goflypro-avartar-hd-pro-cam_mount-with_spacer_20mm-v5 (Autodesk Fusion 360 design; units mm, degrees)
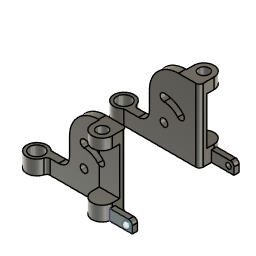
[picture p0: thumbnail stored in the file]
sketch "Skizze1" plane through (0, 0, 0) normal (0, 0, 1) x axis (1, 0, 0)
  line L1 (7.2, 0) -> (-7.2, 0)
  line L2 (7.2, 0) -> (7.2, -2)
  line L3 (-1, 0) -> (-1, 2)
  line L4 (12.8, 2) -> (-8.605, 2)
  line L5 (12.8, 2) -> (12.8, -2)
  line L6 (12.8, 0) -> (7.2, 0)
  line L7 (11, -2) -> (11, 2)
  line L8 (12.8, -2) -> (11, -2)
  circle C1 centre (-10, 0) radius 2
  circle C2 centre (10, -2) radius 1.5
  circle C3 centre (-10, 0) radius 2.8
  circle C4 centre (10, -2) radius 2.8
  point P6 (-7.2, 0)
  point P7 (7.2, -2)
  point P10 (-1, 0)
  point P12 (12.8, -2)
  point P14 (12.8, 0)
  point P15 (11, 2)
  concentric C1 C3
  concentric C2 C4
  coincident C3 P6
  horizontal L1
  coincident C4 P7
  tangent C4 L2
  perpendicular L1 L2
  perpendicular L1 L3
  coincident L1 P10
  coincident C4 P12
  tangent C4 L5
  perpendicular L4 L5
  midpoint L5 P14
  coincident L4 P15
  perpendicular L6 L7
  dimension "d1" diameter C1 = 4
  dimension "d2" diameter C2 = 3
  dimension "d3" diameter C3 = 5.6
  dimension "d4" diameter C4 = 5.6
extrude "Extrusion1" new body sketch "Skizze1" profile of C1 C3 L1 L3 L4 along normal blind 4 bodies "GoFlyPro - Avatar-HD-Pro-cam mount with spacer 20mm - left"
extrude "Extrusion5" new body sketch "Skizze1" profile of C2 C4 L2 L5 L6 L7 L8 along normal blind 4 bodies "GoFlyPro - Avatar-HD-Pro-cam mount with spacer 20mm - left"
extrude "Extrusion8" add sketch "Skizze1" profile of C4 L1 L3 L4 L5 L6 L7 along normal blind 20 bodies "GoFlyPro - Avatar-HD-Pro-cam mount with spacer 20mm - left"
sketch "Skizze2" plane through (0, 0, 0) normal (0, 1, 0) x axis (1, 0, 0)
  line L1 (7.2, 0) -> (-7.2, 0)
  line L2 (7.2, -4) -> (7.2, 0)
  line L3 (7.2, -20) -> (7.2, -4)
  line L4 (-1, -20) -> (7.2, -20)
  line L5 (-1, -4) -> (-1, -20)
  line L6 (-7.2, -4) -> (-1, -4)
  line L7 (-7.2, 0) -> (-7.2, -4)
  circle C1 centre (3, -6.25) radius 1.05
  circle C2 centre (3, -6.25) radius 4.95
  circle C3 centre (3, -6.25) radius 7.05
  circle C4 centre (3, -12.25) radius 1.05
  circle C5 centre (7.5963, -10.1067) radius 1.05
  concentric C1 C2
  concentric C2 C3
  dimension "d8" diameter C1 = 2.1
  dimension "d32" diameter C4 = 2.1
  dimension "d64" diameter C5 = 2.1
extrude "Extrusion2" cut sketch "Skizze2" profile of C1 C2 C3 C4 C5 L3 along normal blind 2
fillet "Abrundung12" radius 1
work_plane "Arbeitsebene" AlongDistance 12
sketch "Skizze3" plane through (0, 0, 20) normal (0, 0, 1) x axis (-1, 0, 0)
  line L1 (-12.8, -2) -> (-12.8, 2)
  line L2 (-7, -2) -> (-12.8, -2)
  line L3 (-7, 0) -> (-7, -2)
  line L4 (-7.2, 0) -> (-7, 0)
  line L5 (-11.9596, 0) -> (-7.2, 0)
  line L6 (1, 0) -> (1, -2)
  line L7 (-7.2, 0) -> (1, 0)
  line L8 (-12.8, 0) -> (-7.2, 0)
  line L9 (-12.8, -2) -> (-12.8, 0)
  line L10 (1, -2) -> (-12.8, -2)
  line L11 (-11.9596, 0) -> (-12.8, 0)
  line L12 (-12.8, 2) -> (-12.8, 0)
  line L13 (-8.0404, 0) -> (-7.2, 0)
  line L14 (-7.2, 2) -> (-7.2, 0)
  circle C1 centre (-10, 2) radius 1.5
  circle C2 centre (-10, 2) radius 2.8
  arc A1 centre (-10, 2) radius 2.8 clockwise from (-11.9596, 0) to (-12.8, 2)
  point P14 (-12.8, 0)
  point P16 (-12.8, 0)
  point P2 (-11.9596, 0)
  point P17 (-11.9596, 0)
  point P18 (-12.8, 0)
  point P3 (-12.8, 2)
  point P19 (-12.8, 2)
  point P13 (-7.2, 0)
  point P20 (-7.2, 0)
  point P21 (-8.0404, 0)
  point P22 (-7.2, 0)
  point P23 (-7.2, 2)
  concentric C1 C2
  coincident P14 P16
  coincident P2 P17
  coincident P14 P18
  coincident P3 P19
  coincident P13 P20
  coincident C2 P21
  coincident L5 P21
  coincident P13 P22
  coincident C2 P23
  tangent C2 L14
  dimension "d77" diameter C1 = 3
  dimension "d78" diameter C2 = 5.6
extrude "Extrusion10" add sketch "Skizze3" profile of L1 C1 C2 L5 A1 L8 L11 L12 L13 L14 against normal blind 3
extrude "Extrusion11" cut sketch "Skizze1" profile of C2 L7 L8 along normal blind 3.2
extrude "Extrusion12" cut sketch "Skizze3" profile of C1 against normal blind 3
sketch "Skizze4" plane through (0, 0, 0) normal (0, 0, 1) x axis (1, 0, 0)
  line L1 (12.5, -2.7) -> (19, -2.7)
  line L2 (12.5, -1.3) -> (12.5, -2.7)
  line L3 (19, -1.3) -> (12.5, -1.3)
  line L4 (19, -2.7) -> (19, -1.3)
  horizontal L1
  vertical L2
  horizontal L3
  vertical L4
extrude "Extrusion13" add sketch "Skizze4" along normal blind 3
sketch "Skizze5" plane through (0, -2.7, 0) normal (0, -1, 0) x axis (1, 0, 0)
  line L1 (19, 0) -> (12.7111, 0)
  line L2 (19, 3) -> (19, 0)
  line L3 (12.7111, 3) -> (19, 3)
  line L4 (12.7111, 0) -> (12.7111, 3)
  circle C1 centre (17.5, 1.5) radius 0.75
  dimension "d93" diameter C1 = 1.5
extrude "Extrusion14" cut sketch "Skizze5" profile of C1 against normal blind 1.4
fillet "Abrundung22" radius 1
fillet "Abrundung24" radius 8
fillet "Abrundung25" radius 3
mirror "Spiegeln" mirrorStitchTolerance 0.1 bodies "GoFlyPro - Avatar-HD-Pro-cam mount with spacer 20mm - right"
fillet "Abrundung26" radius 1
named bodies: "GoFlyPro - Avatar-HD-Pro-cam mount with spacer 20mm - left", "GoFlyPro - Avatar-HD-Pro-cam mount with spacer 20mm - right"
